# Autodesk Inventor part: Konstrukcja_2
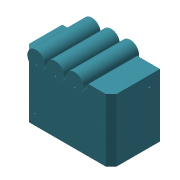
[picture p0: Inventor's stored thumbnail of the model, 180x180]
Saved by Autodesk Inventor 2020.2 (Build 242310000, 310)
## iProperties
Created: 2014-07
Part Number: Konstrukcja_2
Material: Ogólny
Document SubType Name: Modeling
Designer: F.Stasiak
Density: 1 g/cm^3
Appearance: Niebieska z odcieniem szarości
Catalog Web Link: www.expertbooks.pl
Manager: www.cadconsulting.pl
Company: Fabian Stasiak CAD Consulting
Author: F.Stasiak
Subject: Zbiór ćwiczeń. Autodesk Inventor 2020. Kurs Professional
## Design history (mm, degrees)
sketch "Szkic1"
  geometry: L1 (0, 0)-(2500, 0); L2 (2500, 0)-(2500, 1400); L3 (2500, 1400)-(1400, 1400); L4 (1400, 1400)-(1400, 1100); L5 (1400, 1100)-(0, 1100); L6 (0, 1100)-(0, 0)
  constraints: 12 end point, 4 perpendicular, 1 horizontal
  dimensions: "d0" = 2500 distance of L1.start L1.end; "d6" = 1100 distance of L2.end L3.end; "d7" = 300 distance of L3.end L4.end
extrude "Wyciągnięcie proste1" new body sketch "Szkic1" distance "d8" = 1800; taper "d9" = 0 deg
sketch "Szkic3"
  geometry: L1 (0, 0)-(2500, 0) reference; L2 (0, 0)-(0, 1800) reference; 1 further point
  dimensions: "d14" = 300 distance from line of point (300, 300) L1; "d15" = 300 distance from line of L2 point (300, 300)
hole "Otwór1" sketch "Szkic3" at (300, 300) diameter "d16" = 50; stored, may be unused: countersink angle "d20" = 90 deg, drill point angle "d22" = 118 deg; dims "d17" = 6, "d18" = 4, "d19" = 2, "d21" = 100
node "Płaszczyzna konstrukcyjna16"
sketch "Szkic8"
  geometry: L1 (0, 0)-(2500, 0) reference; L2 (1400, 0)-(0, 0) reference; C1 r 250 at (500, 0); C2 r 250 at (1050, 0); C3 r 250 at (1600, 0); 1 further point
  constraints: 4 point on line, 3 centre point
  dimensions: "d64" = 500 diameter of C1; "d65" = 500 diameter of C2; "d66" = 500 diameter of C3; "d67" = 500 distance of L1.start C1.centre; "d68" = 550 distance of C2.centre C1.centre; "d69" = 550 distance of C3.centre C2.centre (= d68)
extrude "Wyciągnięcie proste5" join sketch "Szkic8" distance "d70" = 700; taper "d71" = 0 deg; dims "d122" = 900, "d123" = 0
sketch "Szkic10"
  geometry: L1 (0, 0)-(1100, 0); L2 (1100, 0)-(1100, -120); L3 (1100, -120)-(0, -120); L4 (0, -120)-(0, 0); C1 r 250 at (0, 0) reference; C2 r 250 at (550, 0) reference; C3 r 250 at (1100, 0) reference; 4 further points
  constraints: 8 end point, 3 coincident, 2 parallel, 1 horizontal, 1 midpoint, 1 perpendicular
  dimensions: "d81" = 120 distance of L1.end L2.end
hole "Otwór6" sketch "Szkic10" at (0, -120), (550, -120), (1100, -120) diameter "d82" = 50; stored, may be unused: countersink angle "d86" = 90 deg, drill point angle "d88" = 118 deg; dims "d83" = 6, "d84" = 4, "d85" = 2, "d87" = 100
hole "Otwór7" diameter "d94" = 50; stored, may be unused: countersink angle "d98" = 90 deg, drill point angle "d100" = 118 deg; dims "d92" = 300, "d93" = 300, "d95" = 6, "d96" = 4, "d97" = 2, "d99" = 100
chamfer "Faza1" distance "d119" = 150; stored, may be unused: second distance "d120" = 2, angle "d121" = 45 deg
node "Bryła1"
